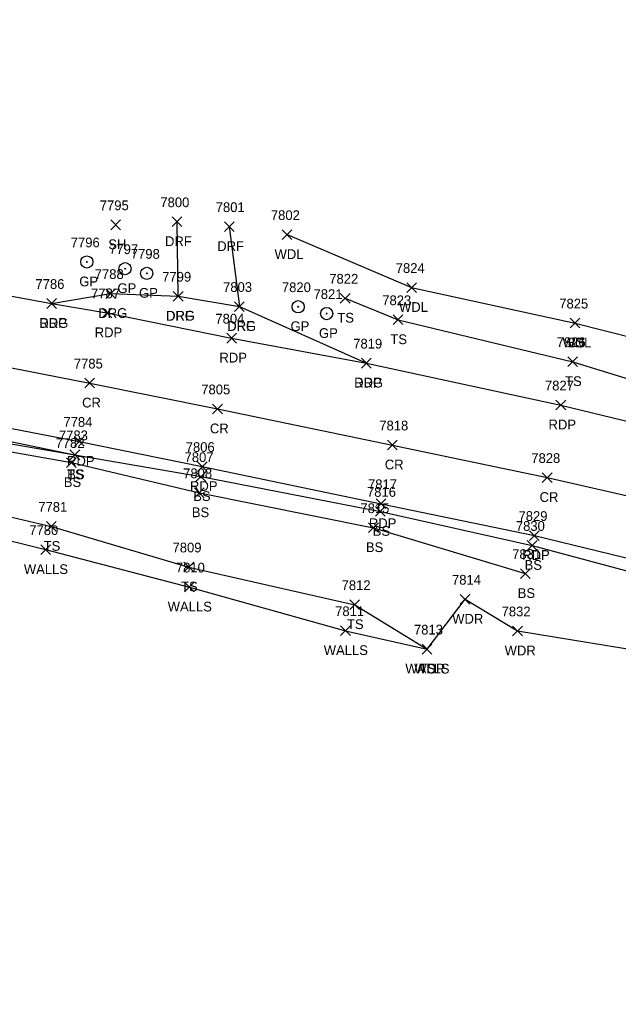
# Model space of a CAD drawing. Extents: x 1611797 to 1633212, y 298978 to 305475.
# Drawn here: x 1625836.4 to 1625959.2, y 304052.6 to 304255.9 of the extents above; entities that cross this region are included whole.
import ezdxf

# ---------------------------------------------------------------- set-up
doc = ezdxf.new("R2010")
doc.units = 0
for name, color, linetype in [('L_A', 7, 'Continuous'), ('L_I', 7, 'Continuous'), ('L_TIC', 7, 'Continuous'), ('LAWA', 7, 'Continuous'), ('LELB', 7, 'Continuous'), ('LWS', 7, 'Continuous'), ('P_A', 7, 'Continuous'), ('P_I', 7, 'Continuous'), ('P_TIC', 7, 'Continuous'), ('PET', 7, 'Continuous'), ('PRC', 7, 'Continuous'), ('R_A', 7, 'Continuous'), ('R_I', 7, 'Continuous'), ('R_TIC', 7, 'Continuous'), ('RDF', 7, 'Continuous'), ('RDG', 7, 'Continuous'), ('RGP', 7, 'Continuous')]:
    doc.layers.add(name, color=color, linetype=linetype)

msp = doc.modelspace()

# ---------------------------------------------------------------- linework, layer by layer
at = {"layer": 'L_TIC'}
for points in [[(1625855.04, 304212.83), (1625857.04, 304214.83)], [(1625857.04, 304212.83), (1625855.04, 304214.83)], [(1625890.25, 304210.81), (1625892.25, 304212.81)], [(1625892.25, 304210.81), (1625890.25, 304212.81)], [(1625915.82, 304199.95), (1625917.82, 304201.95)], [(1625917.82, 304199.95), (1625915.82, 304201.95)], [(1625902.17, 304197.75), (1625904.17, 304199.75)], [(1625904.17, 304197.75), (1625902.17, 304199.75)], [(1625913.05, 304193.33), (1625915.05, 304195.33)], [(1625915.05, 304193.33), (1625913.05, 304195.33)], [(1625949.4, 304192.65), (1625951.4, 304194.65)], [(1625951.4, 304192.65), (1625949.4, 304194.65)], [(1625949.4, 304192.65), (1625951.4, 304194.65)], [(1625951.4, 304192.65), (1625949.4, 304194.65)], [(1625948.92, 304184.73), (1625950.92, 304186.73)], [(1625950.92, 304184.73), (1625948.92, 304186.73)], [(1625846.65, 304165.6), (1625848.65, 304167.6)], [(1625848.65, 304165.6), (1625846.65, 304167.6)], [(1625846.65, 304165.6), (1625848.65, 304167.6)], [(1625848.65, 304165.6), (1625846.65, 304167.6)], [(1625845.95, 304164.02), (1625847.95, 304166.02)], [(1625847.95, 304164.02), (1625845.95, 304166.02)], [(1625872.53, 304161.13), (1625874.53, 304163.13)], [(1625874.53, 304161.13), (1625872.53, 304163.13)], [(1625872.24, 304157.81), (1625874.24, 304159.81)], [(1625874.24, 304157.81), (1625872.24, 304159.81)], [(1625909.4, 304153.99), (1625911.4, 304155.99)], [(1625911.4, 304153.99), (1625909.4, 304155.99)], [(1625841.85, 304150.91), (1625843.85, 304152.91)], [(1625843.85, 304150.91), (1625841.85, 304152.91)], [(1625907.99, 304150.65), (1625909.99, 304152.65)], [(1625909.99, 304150.65), (1625907.99, 304152.65)], [(1625940.58, 304147), (1625942.58, 304149)], [(1625942.58, 304147), (1625940.58, 304149)], [(1625840.65, 304146.14), (1625842.65, 304148.14)], [(1625842.65, 304146.14), (1625840.65, 304148.14)], [(1625870.07, 304142.58), (1625872.07, 304144.58)], [(1625872.07, 304142.58), (1625870.07, 304144.58)], [(1625939.16, 304141.23), (1625941.16, 304143.23)], [(1625941.16, 304141.23), (1625939.16, 304143.23)], [(1625870.19, 304138.46), (1625872.19, 304140.46)], [(1625872.19, 304138.46), (1625870.19, 304140.46)], [(1625904.13, 304134.84), (1625906.13, 304136.84)], [(1625906.13, 304134.84), (1625904.13, 304136.84)], [(1625926.8, 304135.96), (1625928.8, 304137.96)], [(1625928.8, 304135.96), (1625926.8, 304137.96)], [(1625902.24, 304129.51), (1625904.24, 304131.51)], [(1625904.24, 304129.51), (1625902.24, 304131.51)], [(1625937.56, 304129.45), (1625939.56, 304131.45)], [(1625939.56, 304129.45), (1625937.56, 304131.45)], [(1625918.99, 304125.72), (1625920.99, 304127.72)], [(1625920.99, 304125.72), (1625918.99, 304127.72)], [(1625918.99, 304125.72), (1625920.99, 304127.72)], [(1625920.99, 304125.72), (1625918.99, 304127.72)], [(1625918.99, 304125.72), (1625920.99, 304127.72)], [(1625920.99, 304125.72), (1625918.99, 304127.72)]]:
    msp.add_lwpolyline(points, dxfattribs=at)
at = {"layer": 'LAWA'}
for points in [[(1625891.25, 304211.81), (1625916.82, 304200.95), (1625950.4, 304193.65)], [(1625919.99, 304126.72), (1625927.8, 304136.96), (1625938.56, 304130.45), (1625993.83, 304121.47), (1626027.53, 304113.55), (1626073.32, 304098.73), (1626125.26, 304080.94), (1626164.23, 304071.39), (1626202.03, 304059.49), (1626244.32, 304056.42), (1626267.75, 304052.6)]]:
    msp.add_lwpolyline(points, dxfattribs=at)
at = {"layer": 'LELB'}
for points in [[(1625615.3, 304209.46), (1625616.6, 304213.59), (1625628.89, 304212.75), (1625666.38, 304202.9), (1625700.28, 304195.04), (1625739.78, 304185.57), (1625775.03, 304180.78), (1625806.38, 304175.19), (1625847.65, 304166.6)], [(1625616.78, 304212.23), (1625616.57, 304210.6), (1625627.25, 304207.17), (1625665.77, 304197.37), (1625698.87, 304189.53), (1625739.34, 304180.81), (1625773.92, 304176.12), (1625806.27, 304172.23), (1625846.95, 304165.02), (1625873.24, 304158.81), (1625908.99, 304151.65), (1625940.16, 304142.23)], [(1625616.78, 304212.23), (1625627.95, 304210), (1625665.76, 304199.2), (1625699.61, 304192.01), (1625739.43, 304182.25), (1625774.64, 304179.41), (1625806.25, 304173.74), (1625847.65, 304166.6), (1625873.53, 304162.13), (1625910.4, 304154.99), (1625941.58, 304148), (1625998.07, 304132.87), (1626026.09, 304121.17), (1626075.62, 304107.35), (1626127.5, 304094.38), (1626168.28, 304088.26), (1626207.2, 304079.89), (1626248.46, 304072.51), (1626270.11, 304064), (1626301.67, 304064.82), (1626335.88, 304063.87), (1626356.59, 304058.92), (1626364.52, 304060.22), (1626370.3, 304066.63)], [(1625615.3, 304209.46), (1625626.17, 304204.91), (1625665.38, 304194.23), (1625698.23, 304185.67), (1625738.37, 304175.34), (1625771.73, 304167.79), (1625804.42, 304160.94), (1625842.85, 304151.91), (1625871.07, 304143.58), (1625905.13, 304135.84), (1625919.99, 304126.72)], [(1625903.17, 304198.75), (1625914.05, 304194.33), (1625949.92, 304185.73), (1626008.58, 304167.66), (1626035.38, 304165.88), (1626087.22, 304150.1), (1626105.43, 304147.4), (1626119.92, 304157)], [(1625950.4, 304193.65), (1626008.13, 304179.09), (1626035.57, 304168.83), (1626089.95, 304153.74), (1626111.09, 304152.05), (1626116.66, 304158.39)]]:
    msp.add_lwpolyline(points, dxfattribs=at)
at = {"layer": 'LWS'}
msp.add_lwpolyline([(1625751.18, 304168.12), (1625770.95, 304163.71), (1625804.42, 304156.44), (1625841.65, 304147.14), (1625871.19, 304139.46), (1625903.24, 304130.51), (1625919.99, 304126.72)], dxfattribs=at)
at = {"layer": 'P_TIC'}
for points in [[(1625841.89, 304196.67), (1625843.89, 304198.67)], [(1625843.89, 304196.67), (1625841.89, 304198.67)], [(1625853.25, 304194.75), (1625855.25, 304196.75)], [(1625855.25, 304194.75), (1625853.25, 304196.75)], [(1625878.86, 304189.56), (1625880.86, 304191.56)], [(1625880.86, 304189.56), (1625878.86, 304191.56)], [(1625906.53, 304184.43), (1625908.53, 304186.43)], [(1625908.53, 304184.43), (1625906.53, 304186.43)], [(1625849.71, 304180.33), (1625851.71, 304182.33)], [(1625851.71, 304180.33), (1625849.71, 304182.33)], [(1625946.46, 304175.83), (1625948.46, 304177.83)], [(1625948.46, 304175.83), (1625946.46, 304177.83)], [(1625875.96, 304175.03), (1625877.96, 304177.03)], [(1625877.96, 304175.03), (1625875.96, 304177.03)], [(1625847.58, 304168.36), (1625849.58, 304170.36)], [(1625849.58, 304168.36), (1625847.58, 304170.36)], [(1625911.88, 304167.62), (1625913.88, 304169.62)], [(1625913.88, 304167.62), (1625911.88, 304169.62)], [(1625872.82, 304163.2), (1625874.82, 304165.2)], [(1625874.82, 304163.2), (1625872.82, 304165.2)], [(1625943.66, 304160.94), (1625945.66, 304162.94)], [(1625945.66, 304160.94), (1625943.66, 304162.94)], [(1625909.55, 304155.56), (1625911.55, 304157.56)], [(1625911.55, 304155.56), (1625909.55, 304157.56)], [(1625941.04, 304149.04), (1625943.04, 304151.04)], [(1625943.04, 304149.04), (1625941.04, 304151.04)]]:
    msp.add_lwpolyline(points, dxfattribs=at)
at = {"layer": 'PET'}
for points in [[(1625586.31, 304255.91), (1625607.81, 304248.69), (1625627.8, 304243.1), (1625663.83, 304233.32), (1625705.69, 304223.32), (1625745.33, 304215.4), (1625782.16, 304208.85), (1625809.84, 304203.75), (1625842.89, 304197.67), (1625854.25, 304195.75), (1625879.86, 304190.56), (1625907.53, 304185.43), (1625947.46, 304176.83), (1626006.88, 304162.45), (1626033.84, 304156.45), (1626086.36, 304144.08), (1626106.38, 304139.71), (1626124.35, 304136.3), (1626145.01, 304132.43), (1626173.44, 304126.61)], [(1625582, 304228.03), (1625604.38, 304221.93), (1625623.11, 304216.8), (1625629.99, 304215.01), (1625666.4, 304205.5), (1625700.68, 304197.74), (1625740.65, 304189.9), (1625775.69, 304183.22), (1625806.63, 304177.45), (1625848.58, 304169.36), (1625873.82, 304164.2), (1625910.55, 304156.56), (1625942.04, 304150.04), (1625999.43, 304136.07), (1626027.66, 304129.84), (1626078.84, 304117.76), (1626130, 304106.69), (1626169.93, 304098.98)]]:
    msp.add_lwpolyline(points, dxfattribs=at)
at = {"layer": 'PRC'}
msp.add_lwpolyline([(1625591.76, 304239.18), (1625621.07, 304231.02), (1625660.99, 304220.4), (1625703.46, 304210.63), (1625742.09, 304202.26), (1625779.19, 304195.16), (1625807.69, 304189.72), (1625850.71, 304181.33), (1625876.96, 304176.03), (1625912.88, 304168.62), (1625944.66, 304161.94), (1626003.2, 304148.59), (1626030.53, 304142.49), (1626082.66, 304130.28), (1626134.01, 304119.49), (1626173.14, 304111.57)], dxfattribs=at)
at = {"layer": 'R_TIC'}
for points in [[(1625867.64, 304213.45), (1625869.64, 304215.45)], [(1625869.64, 304213.45), (1625867.64, 304215.45)], [(1625878.36, 304212.45), (1625880.36, 304214.45)], [(1625880.36, 304212.45), (1625878.36, 304214.45)], [(1625854, 304198.71), (1625856, 304200.71)], [(1625856, 304198.71), (1625854, 304200.71)], [(1625867.87, 304198.16), (1625869.87, 304200.16)], [(1625869.87, 304198.16), (1625867.87, 304200.16)], [(1625867.87, 304198.16), (1625869.87, 304200.16)], [(1625869.87, 304198.16), (1625867.87, 304200.16)], [(1625841.89, 304196.67), (1625843.89, 304198.67)], [(1625843.89, 304196.67), (1625841.89, 304198.67)], [(1625880.44, 304196.05), (1625882.44, 304198.05)], [(1625882.44, 304196.05), (1625880.44, 304198.05)], [(1625880.44, 304196.05), (1625882.44, 304198.05)], [(1625882.44, 304196.05), (1625880.44, 304198.05)], [(1625906.53, 304184.43), (1625908.53, 304186.43)], [(1625908.53, 304184.43), (1625906.53, 304186.43)]]:
    msp.add_lwpolyline(points, dxfattribs=at)
at = {"layer": 'RDF'}
for points in [[(1625868.87, 304199.16), (1625868.64, 304214.45)], [(1625879.36, 304213.45), (1625881.44, 304197.05)]]:
    msp.add_lwpolyline(points, dxfattribs=at)
at = {"layer": 'RDG'}
msp.add_lwpolyline([(1625842.89, 304197.67), (1625855, 304199.71), (1625868.87, 304199.16), (1625881.44, 304197.05), (1625907.53, 304185.43)], dxfattribs=at)
at = {"layer": 'RGP'}
for p, q in [((1625850.13, 304206.2), (1625850.13, 304206.2)), ((1625857.97, 304204.82), (1625857.97, 304204.82)), ((1625862.42, 304203.86), (1625862.42, 304203.86)), ((1625893.53, 304197.01), (1625893.53, 304197.01)), ((1625899.37, 304195.6), (1625899.37, 304195.6))]:
    msp.add_line(p, q, dxfattribs=at)
for centre, radius in [((1625850.13, 304206.2), 1.25), ((1625850.13, 304206.2), 0.0833), ((1625857.97, 304204.82), 1.25), ((1625857.97, 304204.82), 0.0833), ((1625862.42, 304203.86), 1.25), ((1625862.42, 304203.86), 0.0833), ((1625893.53, 304197.01), 1.25), ((1625893.53, 304197.01), 0.0833), ((1625899.37, 304195.6), 1.25), ((1625899.37, 304195.6), 0.0833)]:
    msp.add_circle(centre, radius, dxfattribs=at)

# ---------------------------------------------------------------- texts
at = {"layer": 'L_A'}
for s, p in [('SH', (1625854.53, 304208.83)), ('WDL', (1625888.67, 304206.81)), ('WDL', (1625914.23, 304195.95)), ('TS', (1625901.57, 304193.75)), ('TS', (1625912.46, 304189.33)), ('WDL', (1625947.81, 304188.65)), ('BS', (1625948.84, 304188.65)), ('TS', (1625948.33, 304180.73)), ('TS', (1625846.06, 304161.6)), ('BS', (1625846.09, 304161.6)), ('BS', (1625845.39, 304160.02)), ('BS', (1625871.97, 304157.13)), ('BS', (1625871.68, 304153.81)), ('BS', (1625908.84, 304149.99)), ('TS', (1625841.25, 304146.91)), ('BS', (1625907.43, 304146.65)), ('BS', (1625940.02, 304143)), ('WALLS', (1625837.19, 304142.14)), ('TS', (1625869.48, 304138.58)), ('BS', (1625938.61, 304137.23)), ('WALLS', (1625866.73, 304134.46)), ('TS', (1625903.54, 304130.84)), ('WDR', (1625925.16, 304131.96)), ('WALLS', (1625898.78, 304125.51)), ('WDR', (1625935.92, 304125.45)), ('WALLS', (1625915.53, 304121.72)), ('WDR', (1625917.35, 304121.72)), ('TS', (1625918.4, 304121.72))]:
    msp.add_text(s, height=2, dxfattribs=at).set_placement(p)
at = {"layer": 'L_I'}
for s, p in [('7795', (1625852.78, 304216.83)), ('7802', (1625887.92, 304214.81)), ('7824', (1625913.56, 304203.95)), ('7822', (1625899.91, 304201.75)), ('7823', (1625910.79, 304197.33)), ('7825', (1625947.14, 304196.65)), ('7825', (1625947.14, 304196.65)), ('7826', (1625946.61, 304188.73)), ('7783', (1625844.39, 304169.6)), ('7783', (1625844.39, 304169.6)), ('7782', (1625843.69, 304168.02)), ('7807', (1625870.19, 304165.13)), ('7808', (1625869.9, 304161.81)), ('7816', (1625907.65, 304157.99)), ('7781', (1625840.15, 304154.91)), ('7815', (1625906.3, 304154.65)), ('7830', (1625938.23, 304151)), ('7780', (1625838.3, 304150.14)), ('7809', (1625867.72, 304146.58)), ('7831', (1625937.47, 304145.23)), ('7810', (1625868.41, 304142.46)), ('7812', (1625902.44, 304138.84)), ('7814', (1625925.11, 304139.96)), ('7811', (1625901.11, 304133.51)), ('7832', (1625935.3, 304133.45)), ('7813', (1625917.3, 304129.72)), ('7813', (1625917.3, 304129.72)), ('7813', (1625917.3, 304129.72))]:
    msp.add_text(s, height=2, dxfattribs=at).set_placement(p)
at = {"layer": 'P_A'}
for s, p in [('RDP', (1625840.37, 304192.67)), ('RDP', (1625851.74, 304190.75)), ('RDP', (1625877.35, 304185.56)), ('RDP', (1625905.02, 304180.43)), ('CR', (1625849.15, 304176.33)), ('RDP', (1625944.94, 304171.83)), ('CR', (1625875.39, 304171.03)), ('RDP', (1625846.06, 304164.36)), ('CR', (1625911.31, 304163.62)), ('RDP', (1625871.31, 304159.2)), ('CR', (1625943.1, 304156.94)), ('RDP', (1625908.04, 304151.56)), ('RDP', (1625939.53, 304145.04))]:
    msp.add_text(s, height=2, dxfattribs=at).set_placement(p)
at = {"layer": 'P_I'}
for s, p in [('7786', (1625839.57, 304200.67)), ('7787', (1625850.99, 304198.75)), ('7804', (1625876.52, 304193.56)), ('7819', (1625904.83, 304188.43)), ('7785', (1625847.45, 304184.33)), ('7827', (1625944.2, 304179.83)), ('7805', (1625873.62, 304179.03)), ('7784', (1625845.32, 304172.36)), ('7818', (1625910.18, 304171.62)), ('7806', (1625870.43, 304167.2)), ('7828', (1625941.4, 304164.94)), ('7817', (1625907.86, 304159.56)), ('7829', (1625938.77, 304153.04))]:
    msp.add_text(s, height=2, dxfattribs=at).set_placement(p)
at = {"layer": 'R_A'}
for s, p in [('DRF', (1625866.18, 304209.45)), ('DRF', (1625876.9, 304208.45)), ('GP', (1625848.57, 304201.2)), ('GP', (1625856.41, 304199.82)), ('GP', (1625860.85, 304198.86)), ('DRG', (1625852.48, 304194.71)), ('DRG', (1625866.36, 304194.16)), ('DRF', (1625866.41, 304194.16)), ('DRG', (1625840.37, 304192.67)), ('DRG', (1625878.93, 304192.05)), ('DRF', (1625878.98, 304192.05)), ('GP', (1625891.96, 304192.01)), ('GP', (1625897.8, 304190.6)), ('DRG', (1625905.02, 304180.43))]:
    msp.add_text(s, height=2, dxfattribs=at).set_placement(p)
at = {"layer": 'R_I'}
for s, p in [('7800', (1625865.22, 304217.45)), ('7801', (1625876.59, 304216.45)), ('7796', (1625846.82, 304209.2)), ('7797', (1625854.71, 304207.82)), ('7798', (1625859.16, 304206.86)), ('7788', (1625851.74, 304202.71)), ('7799', (1625865.6, 304202.16)), ('7799', (1625865.6, 304202.16)), ('7786', (1625839.57, 304200.67)), ('7803', (1625878.1, 304200.05)), ('7803', (1625878.1, 304200.05)), ('7820', (1625890.18, 304200.01)), ('7821', (1625896.68, 304198.6)), ('7819', (1625904.83, 304188.43))]:
    msp.add_text(s, height=2, dxfattribs=at).set_placement(p)

doc.saveas('drawing.dxf')
